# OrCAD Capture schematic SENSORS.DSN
size A
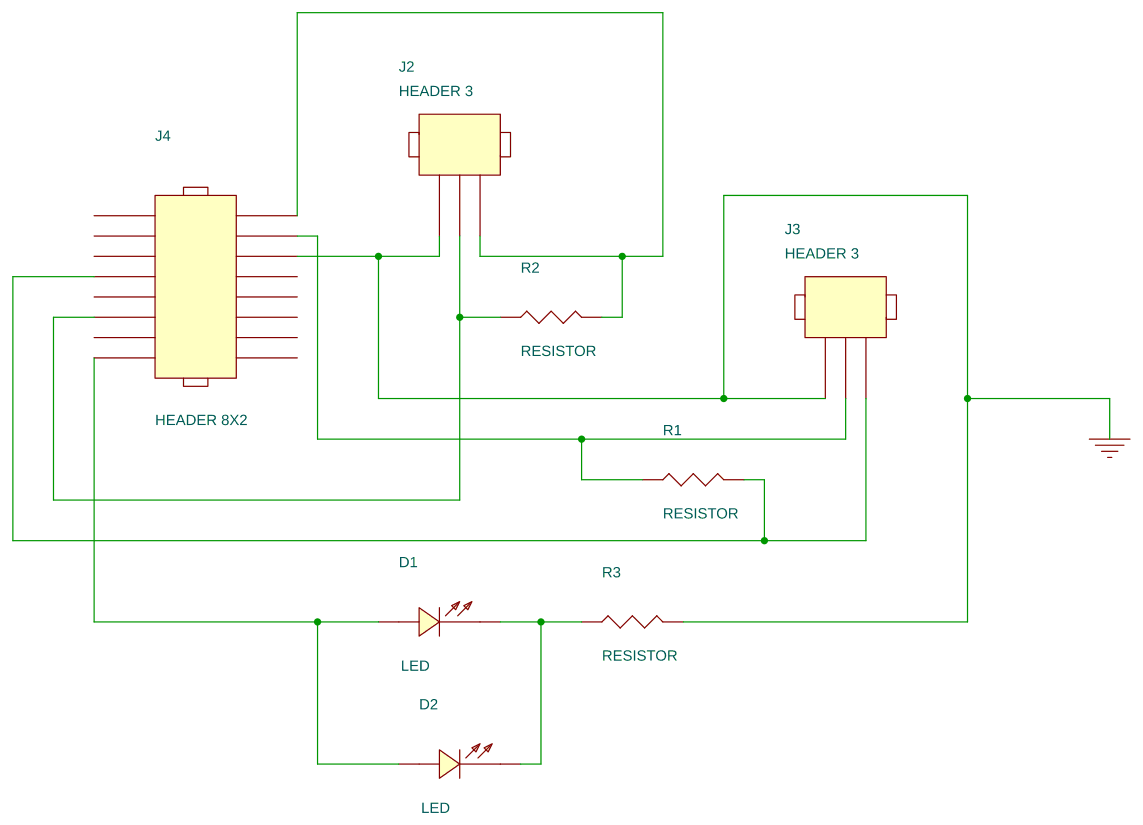
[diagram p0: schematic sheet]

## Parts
D1  LED  [GU-TERMINAL2-200]
D2  LED  [GU-led5mm]
J2  HEADER 3  [GU-MOLEX3]
J3  HEADER 3  [GU-MOLEX3]
J4  HEADER 8X2  [GU-HEADER16]
R1  RESISTOR  [GU-RC500]
R2  RESISTOR  [GU-RC500]
R3  RESISTOR  [GU-RC500]

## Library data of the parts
D1 D2 = LED
J2 J3 = HEADER_3
J4 = HEADER_8X2
R1-R3 = RESISTOR

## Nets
GND: J2.3 J3.3 J4.5 R3.2
N02271: J2.1 J4.1 R2.2
N02364: J2.2 J4.12 R2.1
N02415: J3.2 J4.3 R1.1
N02433: J3.1 J4.8 R1.2
N02506: D1.2(CATHODE) D2.2(CATHODE) R3.1
N04214: D1.1(ANODE) D2.1(ANODE) J4.16

Not connected (* = marked no-connect by the designer): J4 2 4 6 7 9 10 11 13 14 15
